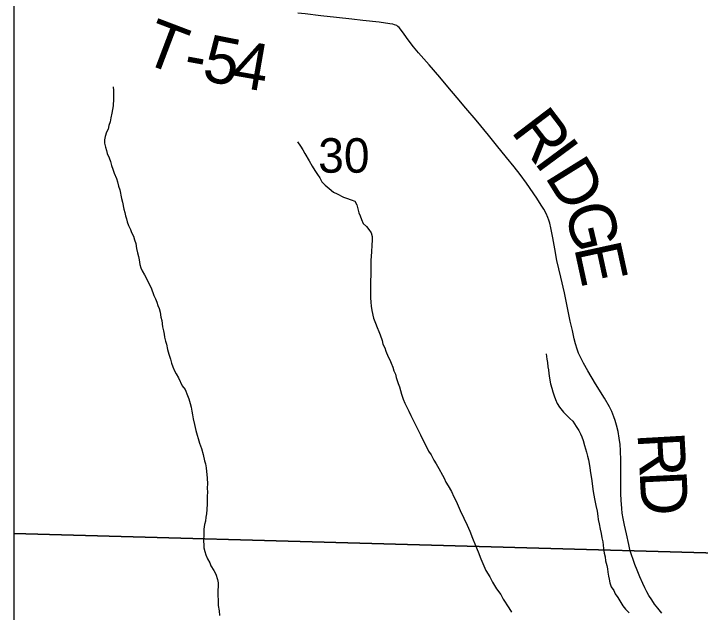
# Model space of a CAD drawing. Extents: x -3.3 to 34, y 0 to 56.8.
# Drawn here: x -3.304 to -2.471, y 32.678 to 33.404 of the extents above; entities that cross this region are included whole.
import ezdxf

# ---------------------------------------------------------------- set-up
doc = ezdxf.new("R2010")
doc.units = 0
for name, color, linetype in [('GM_X_Corporation', 7, 'Continuous'), ('GM_X_Section_Text', 7, 'Continuous'), ('GM_X_Township_Road', 7, 'Continuous'), ('GM_X_Township_Road_Text', 7, 'Continuous'), ('GT_Project_Soil_Layers', 7, 'Continuous'), ('SH_Data', 7, 'Continuous')]:
    doc.layers.add(name, color=color, linetype=linetype)

msp = doc.modelspace()

# ---------------------------------------------------------------- linework, layer by layer
at = {"layer": 'GM_X_Corporation'}
for points in [[(-3.30393, 33.67032), (-3.30393, 32.77402), (-2.31978, 32.74649), (-2.28281, 33.7097), (-3.30126, 33.74009)], [(-3.30393, 32.77402), (-3.30393, 31.76721), (-2.35994, 31.74572), (-2.31978, 32.74649)]]:
    msp.add_lwpolyline(points, close=True, dxfattribs=at)
msp.add_lwpolyline([(0.07113, 33.6404), (-0.68402, 33.66353), (-1.24768, 33.67809), (-1.25588, 33.6783), (-1.26192, 33.67846), (-1.26472, 33.67853), (-1.31578, 33.67985), (-1.4178, 33.68276), (-1.95594, 33.69761), (-3.30393, 33.7379), (-3.30393, 28.07705)], dxfattribs=at)
at = {"layer": 'GM_X_Township_Road'}
for points in [[(-2.56753, 32.86236), (-2.56778, 32.87472), (-2.56836, 32.88179), (-2.56943, 32.88968), (-2.57094, 32.89751), (-2.57274, 32.90557), (-2.57441, 32.91115), (-2.57593, 32.91555), (-2.57866, 32.92182), (-2.58141, 32.92748), (-2.58733, 32.93794), (-2.59824, 32.95558), (-2.60757, 32.97147), (-2.61267, 32.98052), (-2.61694, 32.98857), (-2.61884, 32.99268), (-2.62069, 32.99775), (-2.62268, 33.0039), (-2.62424, 33.01018), (-2.6264, 33.02005), (-2.62883, 33.03169), (-2.63257, 33.04969), (-2.63593, 33.06584), (-2.64053, 33.08496), (-2.6451, 33.10491), (-2.64776, 33.11917), (-2.65025, 33.1325), (-2.65254, 33.14476), (-2.65377, 33.15034), (-2.65484, 33.15413), (-2.65599, 33.15733), (-2.65821, 33.16202), (-2.66117, 33.16736), (-2.66405, 33.17238), (-2.66963, 33.18068), (-2.68213, 33.19876), (-2.68978, 33.20937), (-2.69684, 33.21857), (-2.70607, 33.22998), (-2.71827, 33.24509), (-2.728, 33.25712), (-2.7432, 33.27521), (-2.75552, 33.28986), (-2.76595, 33.30227), (-2.7774, 33.3159), (-2.78718, 33.32757), (-2.80017, 33.34245), (-2.81292, 33.35684), (-2.819, 33.36407), (-2.82532, 33.37262), (-2.83043, 33.37965), (-2.83484, 33.38573), (-2.83636, 33.38759), (-2.83812, 33.3891), (-2.83939, 33.38999), (-2.84193, 33.39108), (-2.84399, 33.39167), (-2.8479, 33.39231), (-2.86075, 33.39399), (-2.88037, 33.39622), (-2.89374, 33.39775), (-2.91263, 33.3999), (-2.93136, 33.40203), (-2.95051, 33.40422), (-2.95952, 33.40524)], [(-2.51789, 32.67727), (-2.52282, 32.68352), (-2.52669, 32.68846), (-2.53016, 32.69364), (-2.53344, 32.69896), (-2.53591, 32.70335), (-2.53836, 32.70801), (-2.54099, 32.71344), (-2.54453, 32.72133), (-2.54789, 32.7293), (-2.55069, 32.73637), (-2.55272, 32.74228), (-2.55456, 32.74805), (-2.55612, 32.75314), (-2.5571, 32.75668), (-2.558, 32.76079), (-2.56081, 32.77377), (-2.5631, 32.78413), (-2.56475, 32.79202), (-2.56581, 32.79852), (-2.56647, 32.80411), (-2.56729, 32.81439), (-2.56762, 32.82211), (-2.5677, 32.83239), (-2.56761, 32.84586), (-2.56747, 32.85927), (-2.56753, 32.86236)]]:
    msp.add_lwpolyline(points, dxfattribs=at)
at = {"layer": 'GT_Project_Soil_Layers'}
for points in [[(-3.18345, 33.3158), (-3.18301, 33.31125), (-3.18287, 33.30137), (-3.18351, 33.29262), (-3.1842, 33.28806), (-3.1849, 33.28387), (-3.18634, 33.27815), (-3.18703, 33.2732), (-3.18849, 33.269), (-3.18956, 33.26443), (-3.19141, 33.2606), (-3.19285, 33.25565), (-3.19394, 33.25145), (-3.19388, 33.24727), (-3.19268, 33.24273), (-3.19148, 33.23857), (-3.19067, 33.23478), (-3.18832, 33.22949), (-3.18675, 33.22534), (-3.18516, 33.22042), (-3.18358, 33.21588), (-3.182, 33.21096), (-3.17926, 33.20454), (-3.17806, 33.20038), (-3.17685, 33.19508), (-3.17528, 33.19092), (-3.17323, 33.18031), (-3.17203, 33.17577), (-3.1704, 33.16743), (-3.16921, 33.16327), (-3.1684, 33.15948), (-3.1672, 33.1557), (-3.1664, 33.15191), (-3.16481, 33.14737), (-3.16248, 33.14284), (-3.16129, 33.13906), (-3.15857, 33.13454), (-3.15738, 33.13037), (-3.1558, 33.12584), (-3.15495, 33.11977), (-3.15374, 33.11447), (-3.15254, 33.10992), (-3.15173, 33.10575), (-3.15089, 33.10045), (-3.1497, 33.09628), (-3.14813, 33.0925), (-3.14541, 33.0876), (-3.13723, 33.07176), (-3.13407, 33.06268), (-3.13211, 33.05853), (-3.13017, 33.05475), (-3.12897, 33.05059), (-3.1274, 33.04681), (-3.1262, 33.04227), (-3.12536, 33.0362), (-3.12417, 33.03242), (-3.1233, 33.02445), (-3.12248, 33.0199), (-3.12166, 33.01573), (-3.12123, 33.01194), (-3.12003, 33.0074), (-3.11884, 33.00361), (-3.11723, 32.99718), (-3.11564, 32.9915), (-3.11366, 32.98545), (-3.11245, 32.98052), (-3.11087, 32.97599), (-3.10892, 32.97145), (-3.10697, 32.96768), (-3.10424, 32.96278), (-3.09956, 32.95296), (-3.09608, 32.94845), (-3.09333, 32.94127), (-3.09138, 32.9375), (-3.08978, 32.93182), (-3.08858, 32.92728), (-3.08776, 32.92235), (-3.08694, 32.9178), (-3.08611, 32.91287), (-3.08488, 32.90605), (-3.08288, 32.89885), (-3.0785, 32.88371), (-3.07613, 32.87691), (-3.07414, 32.86971), (-3.07251, 32.86214), (-3.07132, 32.85835), (-3.0705, 32.85381), (-3.06919, 32.84091), (-3.06909, 32.83407), (-3.06941, 32.8295), (-3.06895, 32.82381), (-3.06927, 32.81962), (-3.06921, 32.81545), (-3.06914, 32.81013), (-3.0698, 32.8029), (-3.07011, 32.79795), (-3.07081, 32.79376), (-3.0715, 32.78882), (-3.07258, 32.785), (-3.07326, 32.77929), (-3.07319, 32.77397)], [(-2.95956, 33.24896), (-2.95607, 33.24368), (-2.95336, 33.23916), (-2.95102, 33.23502), (-2.94559, 33.22597), (-2.94209, 33.21956), (-2.9386, 33.21429), (-2.9355, 33.20939), (-2.93279, 33.20525), (-2.93007, 33.20035), (-2.92623, 33.1966), (-2.92124, 33.19249), (-2.91625, 33.188), (-2.91167, 33.18578), (-2.90403, 33.18209), (-2.90022, 33.18062), (-2.89451, 33.1788), (-2.89031, 33.17696), (-2.8876, 33.17282), (-2.88519, 33.16297), (-2.88362, 33.15919), (-2.88204, 33.15466), (-2.88008, 33.15012), (-2.87624, 33.14638), (-2.87315, 33.14262), (-2.87044, 33.13848), (-2.86924, 33.13432), (-2.86918, 33.12976), (-2.86948, 33.12367), (-2.87013, 33.11569), (-2.87074, 33.10504), (-2.87068, 33.10124), (-2.87098, 33.09554), (-2.87087, 33.08718), (-2.87115, 33.08034), (-2.87109, 33.0754), (-2.87139, 33.07008), (-2.87125, 33.05982), (-2.8708, 33.05451), (-2.87035, 33.04958), (-2.86952, 33.04465), (-2.86749, 33.03518), (-2.86514, 33.02913), (-2.86317, 33.02384), (-2.8612, 33.01892), (-2.85963, 33.01477), (-2.85688, 33.00796), (-2.85606, 33.0038), (-2.85373, 32.99927), (-2.85253, 32.99511), (-2.84978, 32.98831), (-2.84784, 32.98453), (-2.84627, 32.98076), (-2.8443, 32.97584), (-2.8431, 32.9713), (-2.84077, 32.96715), (-2.83996, 32.96336), (-2.83758, 32.9558), (-2.83601, 32.95202), (-2.83361, 32.94293), (-2.83163, 32.93688), (-2.82967, 32.93197), (-2.8246, 32.92216), (-2.82226, 32.91725), (-2.8164, 32.90517), (-2.8125, 32.89763), (-2.81056, 32.89385), (-2.8086, 32.88932), (-2.80471, 32.88216), (-2.8008, 32.87385), (-2.7977, 32.86934), (-2.79458, 32.86292), (-2.79149, 32.8584), (-2.78837, 32.85275), (-2.78371, 32.84483), (-2.78177, 32.84106), (-2.7798, 32.83615), (-2.77709, 32.83162), (-2.77282, 32.82484), (-2.77008, 32.81842), (-2.76813, 32.81465), (-2.76618, 32.8105), (-2.76226, 32.80181), (-2.75796, 32.79237), (-2.75406, 32.78407), (-2.75054, 32.7769), (-2.74739, 32.7682), (-2.74386, 32.75951), (-2.74071, 32.75158), (-2.73756, 32.74326), (-2.7313, 32.72891), (-2.72665, 32.72137), (-2.72314, 32.71496), (-2.71848, 32.70667), (-2.71308, 32.6999), (-2.71034, 32.69424), (-2.70337, 32.6837), (-2.70027, 32.67842)], [(-2.65796, 32.9917), (-2.6575, 32.98563), (-2.65668, 32.98146), (-2.65623, 32.97615), (-2.65542, 32.97236), (-2.65498, 32.96819), (-2.65414, 32.9625), (-2.65291, 32.95567), (-2.65132, 32.95038), (-2.65012, 32.94584), (-2.64854, 32.94092), (-2.64696, 32.93638), (-2.64462, 32.93185), (-2.6419, 32.92733), (-2.63727, 32.92132), (-2.63304, 32.9172), (-2.62958, 32.91344), (-2.62574, 32.91008), (-2.62186, 32.90367), (-2.61838, 32.89878), (-2.61643, 32.89501), (-2.61486, 32.89123), (-2.61328, 32.88669), (-2.61168, 32.88064), (-2.61049, 32.87685), (-2.6093, 32.87269), (-2.60809, 32.86777), (-2.60689, 32.86322), (-2.60607, 32.85906), (-2.60524, 32.85375), (-2.6044, 32.84768), (-2.60358, 32.84313), (-2.60275, 32.83782), (-2.60189, 32.831), (-2.60105, 32.82493), (-2.59942, 32.81621), (-2.59778, 32.80788), (-2.59617, 32.80106), (-2.59533, 32.795), (-2.59489, 32.79082), (-2.59369, 32.7859), (-2.59283, 32.77907), (-2.59163, 32.77415), (-2.5908, 32.76884), (-2.58959, 32.76392), (-2.58915, 32.75975), (-2.58872, 32.75595), (-2.58788, 32.75026), (-2.58668, 32.74572), (-2.58624, 32.74079), (-2.58464, 32.73511), (-2.58383, 32.73094), (-2.58339, 32.72715), (-2.58257, 32.72222), (-2.58176, 32.71843), (-2.58094, 32.71427), (-2.57936, 32.70935), (-2.57626, 32.70483), (-2.57431, 32.70068), (-2.57121, 32.69617), (-2.56772, 32.69014), (-2.56501, 32.68637), (-2.56192, 32.68224), (-2.55731, 32.67774)], [(-3.07319, 32.77397), (-3.07381, 32.76446), (-3.07338, 32.76067), (-3.07332, 32.75649), (-3.07212, 32.75195), (-3.07094, 32.74817), (-3.06897, 32.74325), (-3.06625, 32.73835), (-3.06468, 32.73457), (-3.06119, 32.72892), (-3.05886, 32.72477), (-3.05687, 32.71834), (-3.05605, 32.71417), (-3.05599, 32.70961), (-3.05631, 32.70505), (-3.05606, 32.68681), (-3.05483, 32.68037), (-3.05437, 32.67468)]]:
    msp.add_lwpolyline(points, dxfattribs=at)
at = {"layer": 'SH_Data'}
msp.add_line((-3.30393, 34.87705), (-3.30393, 28.07705), dxfattribs=at)

# ---------------------------------------------------------------- texts
at = {"layer": 'GM_X_Section_Text'}
msp.add_text('30', height=0.041856, rotation=0.00001, dxfattribs=at).set_placement((-2.93464, 33.2116))
at = {"layer": 'GM_X_Township_Road_Text'}
for s, rotation, p in [('T', 339.20218, (-3.15044, 33.3464)), ('5', 348.84009, (-3.07709, 33.32413)), ('4', 350.18038, (-3.04133, 33.31709)), ('-', 349.65996, (-3.09983, 33.32828)), ('R', 307.25473, (-2.70188, 33.26178)), ('I', 306.46242, (-2.67375, 33.2248)), ('D', 301.86715, (-2.66056, 33.20704)), ('G', 283.46287, (-2.63601, 33.16901)), ('E', 282.28244, (-2.62444, 33.12068)), ('R', 273.22942, (-2.54742, 32.89565)), ('D', 272.78056, (-2.5448, 32.84917))]:
    msp.add_text(s, height=0.05682, rotation=rotation, dxfattribs=at).set_placement(p)

doc.saveas('drawing.dxf')
